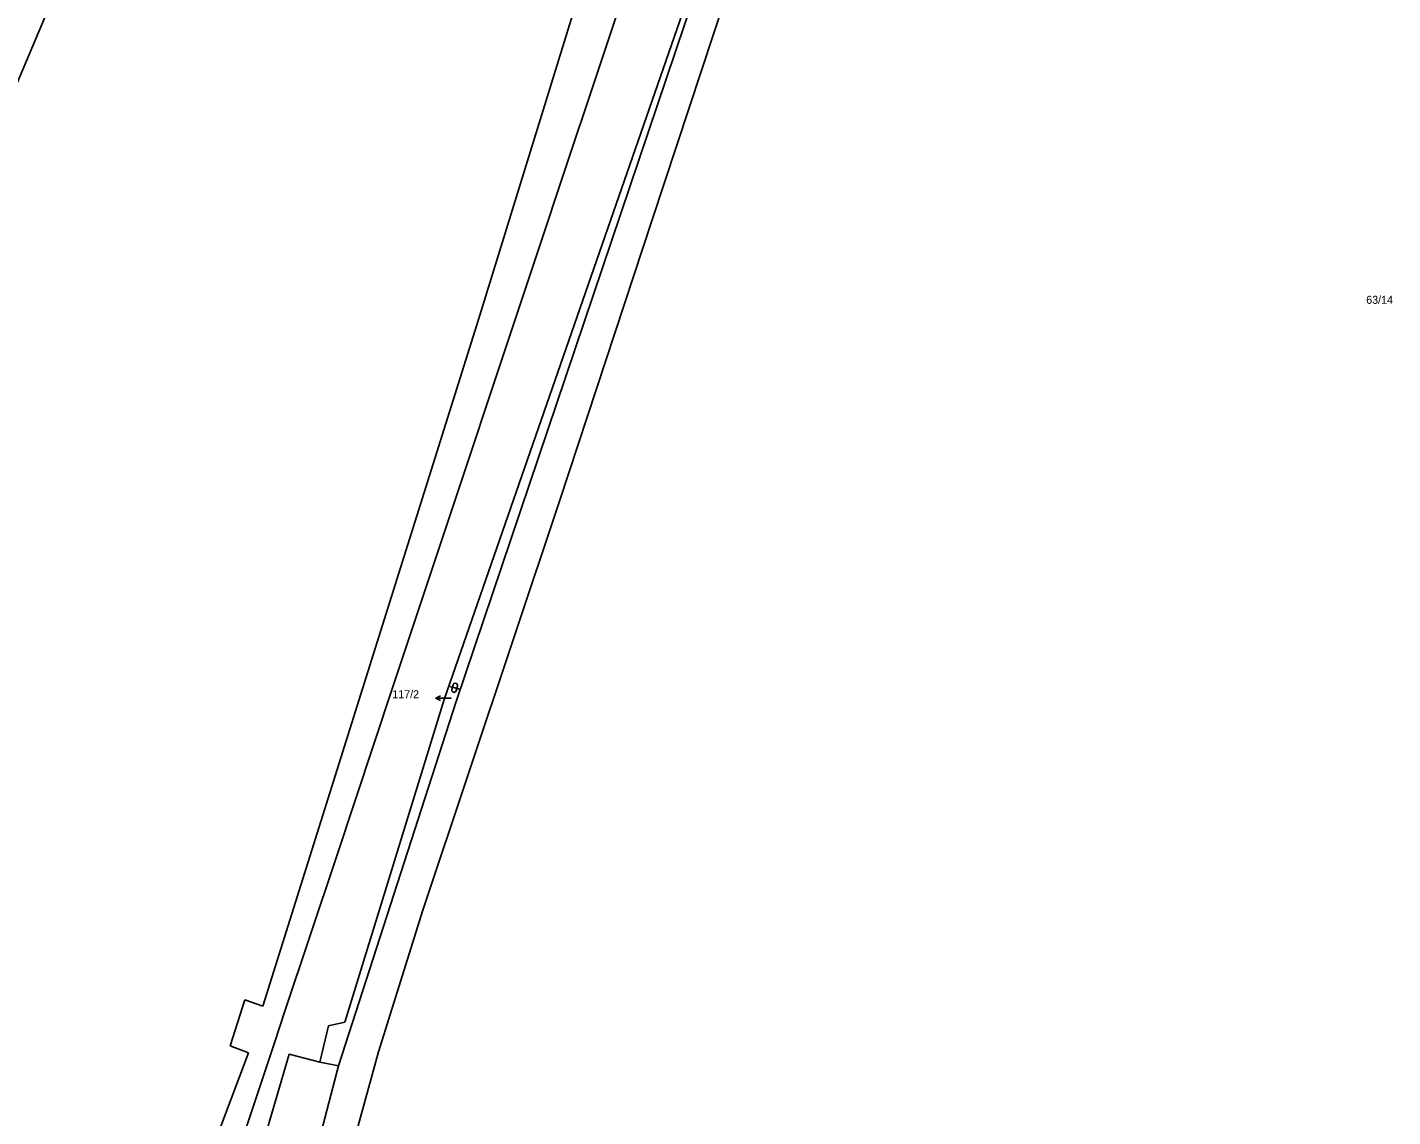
# Model space of a CAD drawing. Extents: x -752343 to -750336, y -1035826 to -1033329.
# Drawn here: x -752019.3 to -751729.2, y -1035246.4 to -1035014.9 of the extents above; entities that cross this region are included whole.
import ezdxf

# ---------------------------------------------------------------- set-up
doc = ezdxf.new("R2010")
doc.units = 0
for name, color, linetype in [('Default', 7, 'Continuous'), ('KN_HRANICE', 7, 'Continuous'), ('KN_KULTURY', 7, 'Continuous'), ('KN_PARCELY', 7, 'Continuous'), ('Vrstva 1', 7, 'Continuous')]:
    doc.layers.add(name, color=color, linetype=linetype)

# ---------------------------------------------------------------- blocks, each defined once
blk = doc.blocks.new('316')
at = {"layer": 'Default'}
for points in [[(-1, 1), (0.27, 1), (1, 1)], [(-0.5, 1.5), (-0.4, 1.79), (-0.15, 1.97), (0.16, 1.97), (0.41, 1.79), (0.51, 1.5), (0.51, 0.5), (0.41, 0.21), (0.16, 0.03), (-0.15, 0.03), (-0.4, 0.21), (-0.5, 0.5), (-0.5, 1.5)]]:
    blk.add_lwpolyline(points, dxfattribs=at)
blk = doc.blocks.new('10292')
at = {"layer": 'Default'}
blk.add_line((0, 3), (0, 0), dxfattribs=at)
blk.add_lwpolyline([(-0.5, 2), (0, 3), (0.5, 2)], dxfattribs=at)

msp = doc.modelspace()

# ---------------------------------------------------------------- linework, layer by layer
at = {"layer": 'KN_HRANICE'}
for p, q in [((-751999.82, -1034975.71), (-752067.65, -1035135.89)), ((-751874.3, -1034995.18), (-751930.72, -1035157.76)), ((-751873.3, -1034995.38), (-751928.14, -1035158.13)), ((-751867.76, -1034999.09), (-751886.57, -1035055.86)), ((-751903.46, -1035012.4), (-751923.41, -1035077.01)), ((-751886.57, -1035055.86), (-751906.24, -1035115.63)), ((-751923.41, -1035077.01), (-751969.21, -1035222.9)), ((-751906.24, -1035115.63), (-751935.26, -1035202.5)), ((-751928.14, -1035158.13), (-751953.14, -1035235.55)), ((-751930.72, -1035157.76), (-751951.84, -1035226.26)), ((-751935.26, -1035202.5), (-751944.7, -1035232.59)), ((-751973.04, -1035221.51), (-751976.18, -1035231.31)), ((-751969.21, -1035222.9), (-751973.04, -1035221.51)), ((-751951.84, -1035226.26), (-751955.3, -1035227.07)), ((-751955.3, -1035227.07), (-751957.13, -1035234.8)), ((-751976.18, -1035231.31), (-751972.29, -1035232.78)), ((-751972.29, -1035232.78), (-752019.52, -1035357.91)), ((-751963.67, -1035233.09), (-752001.66, -1035362.46)), ((-751957.13, -1035234.8), (-751963.67, -1035233.09)), ((-751944.7, -1035232.59), (-751958.36, -1035282.73)), ((-751957.13, -1035234.8), (-751953.14, -1035235.55)), ((-751987.07, -1035365.19), (-751953.14, -1035235.55))]:
    msp.add_line(p, q, dxfattribs=at)
at = {"layer": 'KN_PARCELY'}
msp.add_line((-751929.23, -1035157.47), (-751929.49, -1035157.47), dxfattribs=at)
at = {"layer": 'Vrstva 1'}
msp.add_lwpolyline([(-751987.62, -1035293.38), (-751985.33, -1035286.49), (-751971.34, -1035244.47), (-751966.7, -1035230.47), (-751964.62, -1035224.16), (-751953.68, -1035191.34), (-751941.61, -1035155.08), (-751927.04, -1035111.3), (-751924.06, -1035102.35), (-751922.14, -1035096.59), (-751909.33, -1035058.09), (-751906.33, -1035049.09), (-751897.2, -1035021.76), (-751890.47, -1035001.59)], dxfattribs=at)

# ---------------------------------------------------------------- block references
at = {"layer": 'KN_KULTURY', "rotation": -16.110730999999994}
msp.add_blockref('316', (-751928.77, -1035156.2), dxfattribs=at)
at = {"layer": 'KN_PARCELY', "rotation": 90.01166999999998}
msp.add_blockref('10292', (-751929.49, -1035157.47), dxfattribs=at)

# ---------------------------------------------------------------- texts
at = {"layer": 'KN_PARCELY'}
for s, height, p in [('63/14', 1.7, (-751734.87, -1035073.69)), ('117/2', 1.7, (-751941.74, -1035157.47)), ('117/2', 0.1, (-751929.48, -1035157.47))]:
    msp.add_text(s, height=height, dxfattribs=at).set_placement(p)

doc.saveas('drawing.dxf')
